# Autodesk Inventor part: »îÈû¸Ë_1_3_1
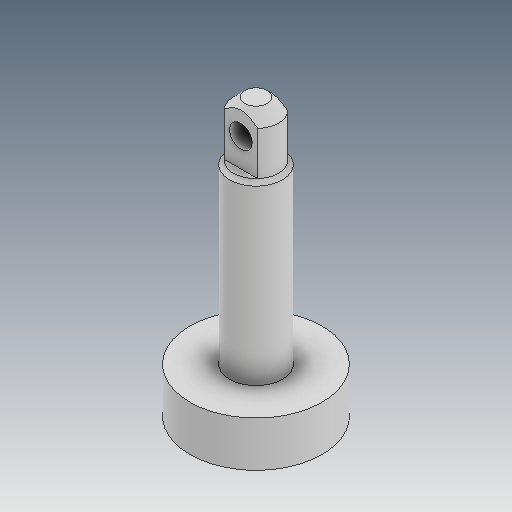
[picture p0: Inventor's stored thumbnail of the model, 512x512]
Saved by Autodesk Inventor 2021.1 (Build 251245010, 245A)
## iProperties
Created: 2019-04
Part Number: »îÈû¸Ë_1_3_1
Material: Ogólny
Document SubType Name: Modeling
Designer: user
Density: 1 g/cm^3
Appearance: Domyślna
Author: user
Revision Number: ÈÎºÎ
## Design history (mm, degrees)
feature "ÊäÈë1"
node "Bryła1"
